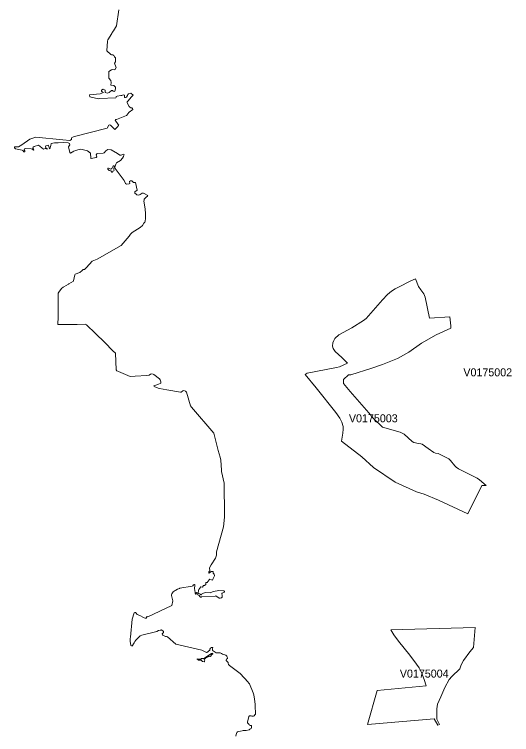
# Model space of a CAD drawing. Extents: x 369010 to 735936, y 6377141 to 6616555.
# Drawn here: x 409515 to 415731, y 6512310 to 6521309 of the extents above; entities that cross this region are included whole.
import ezdxf
from ezdxf.enums import TextEntityAlignment as Align

# ---------------------------------------------------------------- set-up
doc = ezdxf.new("R2010")
doc.units = 0
doc.header["$LTSCALE"] = 40
doc.layers.add('3', color=7, linetype='Continuous', lineweight=13)
doc.layers.add('4', color=7, linetype='Continuous')

msp = doc.modelspace()

# ---------------------------------------------------------------- linework, layer by layer
at = {"layer": '3'}
for points in [[(410820.65, 6521366.8), (410792.35, 6521168.03), (410753.79, 6521105.96), (410739.06, 6521083.46), (410734.59, 6521068.73), (410682.29, 6520991.77), (410679.98, 6520976.37), (410671.7, 6520855.56), (410719.86, 6520807.23), (410730.29, 6520804.58), (410747.34, 6520805.57), (410757.1, 6520797.96), (410767.53, 6520777.6), (410776.96, 6520765.03), (410780.77, 6520748.48), (410777.46, 6520717.69), (410768.19, 6520701.8), (410769.68, 6520688.4), (410788.88, 6520646.69), (410772.33, 6520614.75), (410745.52, 6520621.37), (410730.62, 6520616.9), (410696.86, 6520596.05), (410695.86, 6520585.62), (410694.21, 6520513.79), (410721.68, 6520483.5), (410724.33, 6520460.5), (410722.18, 6520425.91), (410758.42, 6520423.09), (410779.28, 6520401.74), (410777.13, 6520378.08), (410771.5, 6520351.1), (410760.58, 6520347.29), (410748.99, 6520350.11), (410741.87, 6520357.22), (410728.8, 6520356.56), (410698.51, 6520334.05), (410680.97, 6520324.29), (410651.84, 6520333.06), (410651.84, 6520355.07), (410650.18, 6520363.18), (410623.87, 6520376.42), (410605.17, 6520363.84), (410604.67, 6520348.45), (410611.79, 6520340.67), (410628.34, 6520333.56), (410588.45, 6520317.17), (410452.74, 6520305.59), (410458.37, 6520278.61), (410566.44, 6520254.45)], [(410566.44, 6520254.45), (410580.18, 6520259.91), (410781.43, 6520267.69), (410785.9, 6520273.64), (410785.9, 6520284.73), (410800.13, 6520289.7), (410846.8, 6520296.81), (410859.38, 6520296.81), (410864.84, 6520302.28), (410879.74, 6520303.44), (410891.32, 6520298.47), (410893.48, 6520289.7), (410890.66, 6520276.46), (410895.63, 6520271), (410905.06, 6520269.84), (410914.83, 6520273.64), (410930.55, 6520294.5), (410933.36, 6520308.9), (410940.98, 6520316.51), (410971.76, 6520324.79), (411000.23, 6520300.12), (410985.99, 6520289.04), (410979.87, 6520280.26), (410934.36, 6520225.32), (410923.43, 6520216.05), (410923.43, 6520206.12), (410948.09, 6520158.45), (410958.52, 6520149.02), (410972.26, 6520143.56), (410981.52, 6520142.4), (410992.28, 6520134.79), (410994.43, 6520120.55), (410951.73, 6520088.61), (410946.77, 6520081.99), (410918.8, 6520051.87), (410916.48, 6520048.06), (410790.2, 6519995.76), (410778.95, 6519994.94), (410774.31, 6519989.81), (410814.2, 6519935.19), (410819, 6519930.55), (410818.17, 6519921.12), (410804.93, 6519903.25), (410772, 6519871.97), (410720.69, 6519919.3), (410709.77, 6519927.74), (410696.36, 6519927.41), (410673.85, 6519889.01), (410264.56, 6519782.93), (410233.78, 6519773.16), (410227.65, 6519764.39), (410228.81, 6519746.18), (410208.12, 6519733.77), (410121.07, 6519742.71), (409780.96, 6519776.47), (409708.14, 6519749.82), (409606.85, 6519679.98), (409568.12, 6519655.49), (409515.49, 6519653.67), (409514.99, 6519641.09), (409526.74, 6519631.16), (409610.82, 6519613.28), (409621.58, 6519608.32), (409633.49, 6519592.43), (409643.92, 6519590.77), (409644.09, 6519603.68), (409639.12, 6519615.27), (409641.44, 6519629.17), (409656, 6519635.79), (409726.01, 6519629.01), (409740.57, 6519624.87), (409753.48, 6519614.94), (409758.95, 6519617.09), (409745.37, 6519637.78), (409749.68, 6519649.2), (409763.75, 6519659.13), (409817.53, 6519676.67), (409876.78, 6519627.02), (409898.13, 6519635.79), (409922.79, 6519624.54), (409923.62, 6519630.66), (409908.73, 6519641.92), (409904.92, 6519653.67), (409908.56, 6519665.25), (409939.51, 6519677.5), (409948.28, 6519641.58), (409958.71, 6519630.83), (409963.67, 6519641.92), (409965.66, 6519657.14), (409971.62, 6519669.22), (409975.92, 6519697.03), (410015.48, 6519704.48), (410063.97, 6519704.48), (410126.86, 6519707.46), (410186.94, 6519706.3), (410203.32, 6519696.53), (410207.46, 6519677.83), (410191.9, 6519655.82), (410208.12, 6519582.83), (410216.07, 6519577.37)], [(410216.07, 6519577.37), (410256.29, 6519599.55), (410279.79, 6519609.15), (410324.14, 6519620.4), (410345.99, 6519626.19), (410428.24, 6519606.17), (410467.3, 6519577.37), (410468.96, 6519511.17), (410475.91, 6519509.02), (410538.64, 6519522.92), (410547.08, 6519531.19), (410538.64, 6519553.7), (410546.25, 6519568.27), (410555.35, 6519570.42), (410623.54, 6519573.56), (410637.28, 6519579.85), (410656.31, 6519604.84), (410682.13, 6519619.9), (410723.67, 6519616.26), (410804.43, 6519571.08), (410835.22, 6519550.72), (410849.62, 6519548.74), (410879.57, 6519564.96), (410885.37, 6519558.17), (410885.03, 6519548.57), (410878.75, 6519533.18), (410866.66, 6519511.99), (410841.51, 6519484.02), (410790.2, 6519454.4), (410781.76, 6519439.5), (410771.33, 6519400.78), (410773.15, 6519385.88), (410887.19, 6519234.94), (410905.89, 6519198.2), (410914.83, 6519187.11), (410949.42, 6519191.58), (410956.7, 6519195.88), (410955.87, 6519219.55), (410967.95, 6519229.48), (410981.85, 6519229.98), (411005.19, 6519209.62), (411027.37, 6519207.8), (411049.88, 6519112.8), (411020.25, 6519093.27), (411019.59, 6519087.48), (411019.59, 6519076.22), (411037.96, 6519062.49), (411045.9, 6519054.54), (411070.07, 6519051.23), (411087.78, 6519058.35), (411112.77, 6519075.4), (411127.17, 6519076.72), (411184.1, 6519044.61), (411180.46, 6519036.67), (411161.43, 6519027.07), (411138.09, 6519000.92), (411137.26, 6518987.51), (411131.8, 6518974.6), (411149.51, 6518878.78), (411150.01, 6518862.06), (411154.64, 6518834.26), (411153.98, 6518796.36), (411155.97, 6518757.13), (411151.17, 6518725.52), (411144.05, 6518711.29), (411134.12, 6518699.7), (411114.59, 6518671.4), (411086.78, 6518648.06), (410986.16, 6518582.52), (410967.46, 6518563.82), (410951.24, 6518537.51), (410848.29, 6518422.15), (410550.88, 6518249.7), (410488.49, 6518226.86), (410416.99, 6518147.25), (410391.34, 6518120.6), (410376.28, 6518119.78), (410360.88, 6518110.84), (410334.73, 6518085.85), (410274.82, 6518063.34), (410272.34, 6518055.06), (410252.64, 6517981.91), (410253.47, 6517973.97), (410197.53, 6517940.87), (410192.57, 6517937.22), (410134.64, 6517907.27), (410123.55, 6517902.97), (410103.53, 6517885.92), (410071.09, 6517838.42), (410062.48, 6517826.01), (410062.15, 6517713.79), (410061.32, 6517528.93), (410058.01, 6517436.57), (410067.11, 6517433.93), (410300.14, 6517432.77), (410399.94, 6517438.56), (410416.99, 6517431.44), (410530.03, 6517322.21), (410643.56, 6517207.68), (410744.36, 6517105.4)], [(410744.36, 6517105.4), (410777.13, 6517076.44), (410785.4, 6516868.57), (410794.17, 6516856.65), (410818.34, 6516846.22), (410960.84, 6516784.82), (411024.06, 6516787.3), (411171.52, 6516795.91), (411199.33, 6516802.53), (411215.05, 6516814.94), (411233.92, 6516819.08), (411249.64, 6516815.77), (411260.07, 6516809.48), (411328.42, 6516756.19), (411337.52, 6516743.61), (411344.64, 6516717.79), (411345.47, 6516700.91), (411308.06, 6516683.7), (411259.74, 6516669.96), (411260.89, 6516661.69), (411310.71, 6516637.52), (411328.92, 6516633.71), (411419.45, 6516617.99), (411591.74, 6516588.37), (411602, 6516588.2), (411619.87, 6516605.08), (411634.77, 6516609.05), (411652.31, 6516602.93), (411665.22, 6516588.37), (411718.02, 6516418.73), (411730.93, 6516403), (412007.81, 6516076.79), (412063.42, 6515859.49), (412086.43, 6515777.07), (412097.02, 6515738.34), (412102.65, 6515615.37), (412102.81, 6515598.32), (412137.57, 6515452.51), (412140.55, 6515046.04), (412140.22, 6515025.68), (412129.96, 6514907.67), (412041.25, 6514593.55), (412040.42, 6514551.84), (412028.67, 6514516.59), (411973.22, 6514432.35), (411954.52, 6514394.28), (411957, 6514358.04), (411945.75, 6514343.47), (411944.26, 6514330.23), (411948.89, 6514327.25), (411976.37, 6514348.6), (411996.56, 6514349.1), (412001.52, 6514342.81), (412001.86, 6514328.58), (412011.95, 6514315.33), (412015.26, 6514293.49), (411998.71, 6514262.21), (411996.73, 6514249.3), (411991.59, 6514241.52), (411979.68, 6514242.02), (411959.16, 6514251.12), (411948.56, 6514245.66), (411925.23, 6514211.89), (411909.84, 6514209.91), (411908.18, 6514184.42), (411893.12, 6514175.15), (411877.23, 6514174.33), (411867.8, 6514153.64), (411844.63, 6514155.29), (411818.81, 6514122.69), (411816.16, 6514114.91), (411818.48, 6514103.49), (411812.19, 6514086.11), (411815.99, 6514074.86), (411825.26, 6514068.57), (411835.19, 6514070.55), (411841.15, 6514064.43), (411842.31, 6514058.47), (411854.56, 6514054.83), (411863.83, 6514073.04), (411907.85, 6514086.11), (411960.98, 6514083.46), (411972.73, 6514083.96), (412004.5, 6514097.37), (412070.54, 6514110.28), (412135.25, 6514104.81), (412142.37, 6514097.7), (412141.04, 6514088.43), (412113.24, 6514079.33), (412106.79, 6514071.88), (412112.74, 6514048.05), (412110.59, 6514028.52), (412103.31, 6514019.91), (412088.75, 6514013.46), (412073.85, 6514013.95), (412033.47, 6514045.73), (412023.87, 6514039.44), (411854.56, 6514033.48), (411849.26, 6514028.19), (411840.99, 6514028.19)], [(411840.99, 6514028.19), (411832.38, 6514037.29), (411826.42, 6514049.7), (411806.56, 6514058.64), (411801.1, 6514078.5), (411793.65, 6514085.28), (411788.19, 6514083.13), (411788.85, 6514070.72), (411784.88, 6514064.76), (411780.25, 6514065.09), (411776.61, 6514072.21), (411776.11, 6514084.29), (411765.85, 6514137.75), (411770.48, 6514173.66), (411770.48, 6514180.61), (411767.67, 6514185.75), (411755.59, 6514181.94), (411745.82, 6514169.86), (411739.37, 6514164.4), (411582.47, 6514138.25), (411579.16, 6514134.44), (411555.99, 6514126.99), (411533.65, 6514113.59), (411522.89, 6514111.27), (411499.88, 6514092.9), (411483.5, 6514070.06), (411477.04, 6514055.99), (411477.04, 6514050.03), (411497.57, 6513981.51), (411484.99, 6513922.43), (411181.45, 6513782.25), (411173.51, 6513784.23), (411168.38, 6513778.61), (411168.38, 6513767.35), (411163.74, 6513763.21), (411149.84, 6513764.21), (411135.77, 6513767.85), (411127, 6513771.99), (411084.14, 6513798.13), (411051.04, 6513812.53), (411038.46, 6513826.6), (411028.69, 6513834.88), (411019.42, 6513837.19), (411014.29, 6513832.56), (410988.97, 6513752.79), (410967.29, 6513527.7), (410963.15, 6513511.81), (410962.16, 6513486.66), (410963.98, 6513479.21), (410969.61, 6513422.44), (410978.05, 6513417.31), (410987.32, 6513416.81), (410988.64, 6513420.45), (410993.44, 6513424.26), (411005.52, 6513443.79), (411010.82, 6513457.03), (411019.59, 6513471.93), (411033.16, 6513489.14), (411040.11, 6513498.57), (411057.32, 6513514.3), (411086.62, 6513542.76), (411107.14, 6513551.2), (411296.81, 6513597.05), (411315.01, 6513610.45), (411337.36, 6513613.27), (411347.62, 6513616.58), (411353.25, 6513617.4), (411377.91, 6513599.36), (411377.91, 6513587.61), (411374.6, 6513580.17), (411363.84, 6513570.9), (411362.51, 6513563.95), (411365.33, 6513556), (411371.78, 6513554.18), (411404.39, 6513536.97), (411415.97, 6513536.47), (411428.05, 6513532.17), (411534.97, 6513440.32), (411860.35, 6513363.69), (411915.96, 6513336.21), (411922.25, 6513337.37), (411958.33, 6513365.34), (411959.65, 6513375.93), (411968.26, 6513390.33), (411979.35, 6513398.61), (411987.46, 6513399.77), (411990.93, 6513399.77), (411994.41, 6513393.31), (411993.25, 6513388.02), (411990.93, 6513381.73), (411990.44, 6513367.66), (411993.25, 6513361.87), (411999.21, 6513355.41), (412035.78, 6513331.58), (412078.32, 6513333.9), (412082.29, 6513331.58), (412088.75, 6513331.08), (412105.63, 6513324.63), (412114.9, 6513313.54), (412160.41, 6513300.63)], [(412160.41, 6513300.63), (412170.84, 6513289.21), (412173.15, 6513279.28), (412177.12, 6513270.01), (412180.1, 6513261.24), (412167.86, 6513254.29), (412163.06, 6513244.52), (412163.39, 6513237.24), (412167.19, 6513231.12), (412175.47, 6513223.01), (412184.74, 6513216.39), (412187.39, 6513211.42), (412188.54, 6513200.67), (412189.7, 6513188.09), (412203.44, 6513172.53), (412336.84, 6513074.55), (412439.61, 6512965.32), (412443.09, 6512958.53), (412453.52, 6512943.97), (412500.02, 6512830.43), (412503, 6512820.34), (412508.3, 6512806.1), (412515.25, 6512751.16), (412525.35, 6512692.4), (412525.01, 6512662.45), (412526.17, 6512639.28), (412527.83, 6512596.91), (412529.48, 6512589.96), (412529.81, 6512578.54), (412527.99, 6512565.46), (412522.2, 6512556.19), (412512.1, 6512545.44), (412502.67, 6512541.3), (412490.59, 6512540.64), (412481.82, 6512542.46), (412473.87, 6512544.77), (412457.65, 6512546.26), (412453.52, 6512544.77), (412447.23, 6512534.84), (412428.03, 6512467.32), (412429.68, 6512458.88), (412435.81, 6512450.44), (412445.41, 6512442.33), (412445.08, 6512442.33), (412449.54, 6512434.71), (412455.01, 6512428.92), (412461.46, 6512425.11), (412475.36, 6512423.79), (412478.84, 6512419.32), (412480.33, 6512411.21), (412479.17, 6512396.98), (412473.87, 6512387.88), (412467.58, 6512382.08), (412456.99, 6512376.62), (412450.04, 6512371.33), (412411.81, 6512361.06), (412390.96, 6512361.56), (412374.07, 6512360.73), (412361, 6512357.09), (412320.12, 6512350.47), (412309.53, 6512346.66), (412303.4, 6512343.69), (412300.92, 6512341.37), (412299.43, 6512338.22), (412297.12, 6512335.25), (412293.31, 6512327.96), (412282.22, 6512291.55)]]:
    msp.add_lwpolyline(points, dxfattribs=at)
for points in [[(410757.27, 6519418.98), (410751.31, 6519416.66), (410732.11, 6519382.9), (410721.68, 6519377.11), (410692.72, 6519390.02), (410683.45, 6519387.87), (410684.61, 6519376.12), (410698.51, 6519360.72), (410719.37, 6519353.28), (410735.09, 6519338.22), (410741.87, 6519338.38), (410746.34, 6519348.97), (410760.08, 6519355.26), (410763.89, 6519362.05), (410758.92, 6519372.81), (410760.91, 6519412.53)], [(413286, 6516644.97), (413532.93, 6516334.81), (413583.08, 6516262.49), (413609.89, 6516213.17), (413623.8, 6516160.21), (413625.78, 6516124.96), (413621.15, 6516075.8), (413604.43, 6515978.32), (413857.82, 6515780.87), (414003.79, 6515649.63), (414276.87, 6515465.75), (414542.34, 6515345.1), (414637.01, 6515313.49), (414817.08, 6515238.35), (415185.66, 6515068.38), (415359.27, 6515422.89), (415415.04, 6515421.89), (415330.64, 6515493.39), (415300.85, 6515513.75), (415066.82, 6515632.75), (415040.01, 6515650.29), (415020.48, 6515668.83), (414968.52, 6515733.87), (414946.17, 6515754.39), (414813.44, 6515822.08), (414780.01, 6515828.54), (414758.66, 6515836.98), (414688.81, 6515884.15), (414614.5, 6515937.94), (414597.79, 6515943.56), (414566.34, 6515946.21), (414506.92, 6515960.28), (414486.4, 6515971.37), (414386.27, 6516063.06), (414355.65, 6516081.59), (414338.11, 6516088.21), (414117.99, 6516150.44), (414001.97, 6516262.66), (413944.87, 6516332.66), (413710.85, 6516595.32), (413630.08, 6516695.61), (413630.08, 6516747.58), (413693.14, 6516806.17), (413721.94, 6516807.16), (413984.76, 6516890.58), (414118.32, 6516934.77), (414303.19, 6517009.91), (414448.17, 6517089.84), (414604.08, 6517203.05), (414785.96, 6517307.15), (414971.66, 6517386.92), (414969.84, 6517416.71), (414958.75, 6517531.91), (414706.19, 6517515.19), (414652.4, 6517777.02), (414633.7, 6517819.72), (414594.81, 6517867.88), (414568.82, 6517908.76), (414529.76, 6518007.23), (414464.39, 6517975.95), (414325.37, 6517906.28), (414277.2, 6517880.29), (414227.88, 6517850.67), (414180.55, 6517808.79), (414117.49, 6517743.75), (413913.76, 6517511.22), (413880.33, 6517483.41), (413732.7, 6517391.39), (413571.16, 6517305.16), (413522.84, 6517259.65), (413508.94, 6517235.49), (413497.85, 6517204.87), (413492.22, 6517163.99), (413499.67, 6517136.19), (413525.65, 6517098.95), (413607.24, 6517021.99), (413677.91, 6516952.31), (413581.26, 6516904.98), (413542.7, 6516897.86), (413175.94, 6516824.54), (413150.95, 6516809.65)], [(413286, 6516644.97), (413150.95, 6516809.65), (413175.94, 6516824.54), (413542.7, 6516897.86), (413581.26, 6516904.98), (413677.91, 6516952.31), (413607.24, 6517021.99), (413525.65, 6517098.95), (413499.67, 6517136.19), (413492.22, 6517163.99), (413497.85, 6517204.87), (413508.94, 6517235.49), (413522.84, 6517259.65), (413571.16, 6517305.16), (413732.7, 6517391.39), (413880.33, 6517483.41), (413913.76, 6517511.22), (414117.49, 6517743.75), (414180.55, 6517808.79), (414227.88, 6517850.67), (414277.2, 6517880.29), (414325.37, 6517906.28), (414464.39, 6517975.95), (414529.76, 6518007.23), (414568.82, 6517908.76), (414594.81, 6517867.88), (414633.7, 6517819.72), (414652.4, 6517777.02), (414706.19, 6517515.19), (414958.75, 6517531.91), (414969.84, 6517416.71), (414971.66, 6517386.92), (414785.96, 6517307.15), (414604.08, 6517203.05), (414448.17, 6517089.84), (414303.19, 6517009.91), (414118.32, 6516934.77), (413984.76, 6516890.58), (413721.94, 6516807.16), (413693.14, 6516806.17), (413630.08, 6516747.58), (413630.08, 6516695.61), (413710.85, 6516595.32), (413944.87, 6516332.66), (414001.97, 6516262.66), (414117.99, 6516150.44), (414338.11, 6516088.21), (414355.65, 6516081.59), (414386.27, 6516063.06), (414486.4, 6515971.37), (414506.92, 6515960.28), (414566.34, 6515946.21), (414597.79, 6515943.56), (414614.5, 6515937.94), (414688.81, 6515884.15), (414758.66, 6515836.98), (414780.01, 6515828.54), (414813.44, 6515822.08), (414946.17, 6515754.39), (414968.52, 6515733.87), (415020.48, 6515668.83), (415040.01, 6515650.29), (415066.82, 6515632.75), (415300.85, 6515513.75), (415330.64, 6515493.39), (415415.04, 6515421.89), (415359.27, 6515422.89), (415185.66, 6515068.38), (414817.08, 6515238.35), (414637.01, 6515313.49), (414542.34, 6515345.1), (414276.87, 6515465.75), (414003.79, 6515649.63), (413857.82, 6515780.87), (413604.43, 6515978.32), (413621.15, 6516075.8), (413625.78, 6516124.96), (413623.8, 6516160.21), (413609.89, 6516213.17), (413583.08, 6516262.49), (413532.93, 6516334.81)], [(415102.24, 6513181.63), (415128.89, 6513237.74), (415210.15, 6513345.48), (415256.33, 6513398.77), (415274.53, 6513648.19), (414221.26, 6513620.55), (414260.49, 6513557.49), (414318.58, 6513479.71), (414457.27, 6513302.45), (414540.03, 6513191.73), (414573.79, 6513142.74), (414587.03, 6513120.89), (414605.23, 6513084.48), (414638.83, 6512997.76), (414661.34, 6512919.14), (414050.96, 6512862.21), (413927.66, 6512437.2), (414764.78, 6512507.2), (414810.46, 6512429.42), (414831.31, 6512435.71), (414796.39, 6512501.58), (414796.39, 6512630.17), (414806.16, 6512688.93), (414846.87, 6512782.77), (414895.86, 6512899.12), (414948.99, 6512997.1), (414982.58, 6513037.81), (415083.54, 6513130.16)], [(415102.24, 6513181.63), (415083.54, 6513130.16), (414982.58, 6513037.81), (414948.99, 6512997.1), (414895.86, 6512899.12), (414846.87, 6512782.77), (414806.16, 6512688.93), (414796.39, 6512630.17), (414796.39, 6512501.58), (414831.31, 6512435.71), (414810.46, 6512429.42), (414764.78, 6512507.2), (413927.66, 6512437.2), (414050.96, 6512862.21), (414661.34, 6512919.14), (414638.83, 6512997.76), (414605.23, 6513084.48), (414587.03, 6513120.89), (414573.79, 6513142.74), (414540.03, 6513191.73), (414457.27, 6513302.45), (414318.58, 6513479.71), (414260.49, 6513557.49), (414221.26, 6513620.55), (415274.53, 6513648.19), (415256.33, 6513398.77), (415210.15, 6513345.48), (415128.89, 6513237.74)], [(411888.49, 6513250.32), (411905.7, 6513263.39), (411944.26, 6513286.73), (411950.55, 6513289.04), (411966.93, 6513285.4), (411979.35, 6513306.92), (411994.9, 6513318.34), (411994.08, 6513324.79), (411986.63, 6513326.28), (411980.51, 6513323.3), (411881.53, 6513262.56), (411852.24, 6513260.08), (411844.13, 6513251.14), (411810.7, 6513254.29), (411805.57, 6513257.93), (411797.62, 6513253.46), (411805.4, 6513252.47), (411815.99, 6513241.55), (411848.27, 6513239.72), (411865.65, 6513224.99), (411886.33, 6513220.36), (411890.97, 6513221.68), (411894.44, 6513231.78)]]:
    msp.add_lwpolyline(points, close=True, dxfattribs=at)

# ---------------------------------------------------------------- texts
at = {"layer": '4'}
for s, p in [('V0175002', (415432.83, 6516787.07)), ('V0175003', (414001.97, 6516212.65)), ('V0175004', (414638.49, 6513022.41))]:
    msp.add_text(s, height=100, dxfattribs=at).set_placement(p, align=Align.CENTER)

doc.saveas('drawing.dxf')
